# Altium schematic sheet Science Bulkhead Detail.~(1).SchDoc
size B; Organization: Monterey Bay Aquarium Research Institute; Address1: 7700 Sandholdt Rd; Address2: Moss Landing, CA 95039-9644; CompanyName: MBARI
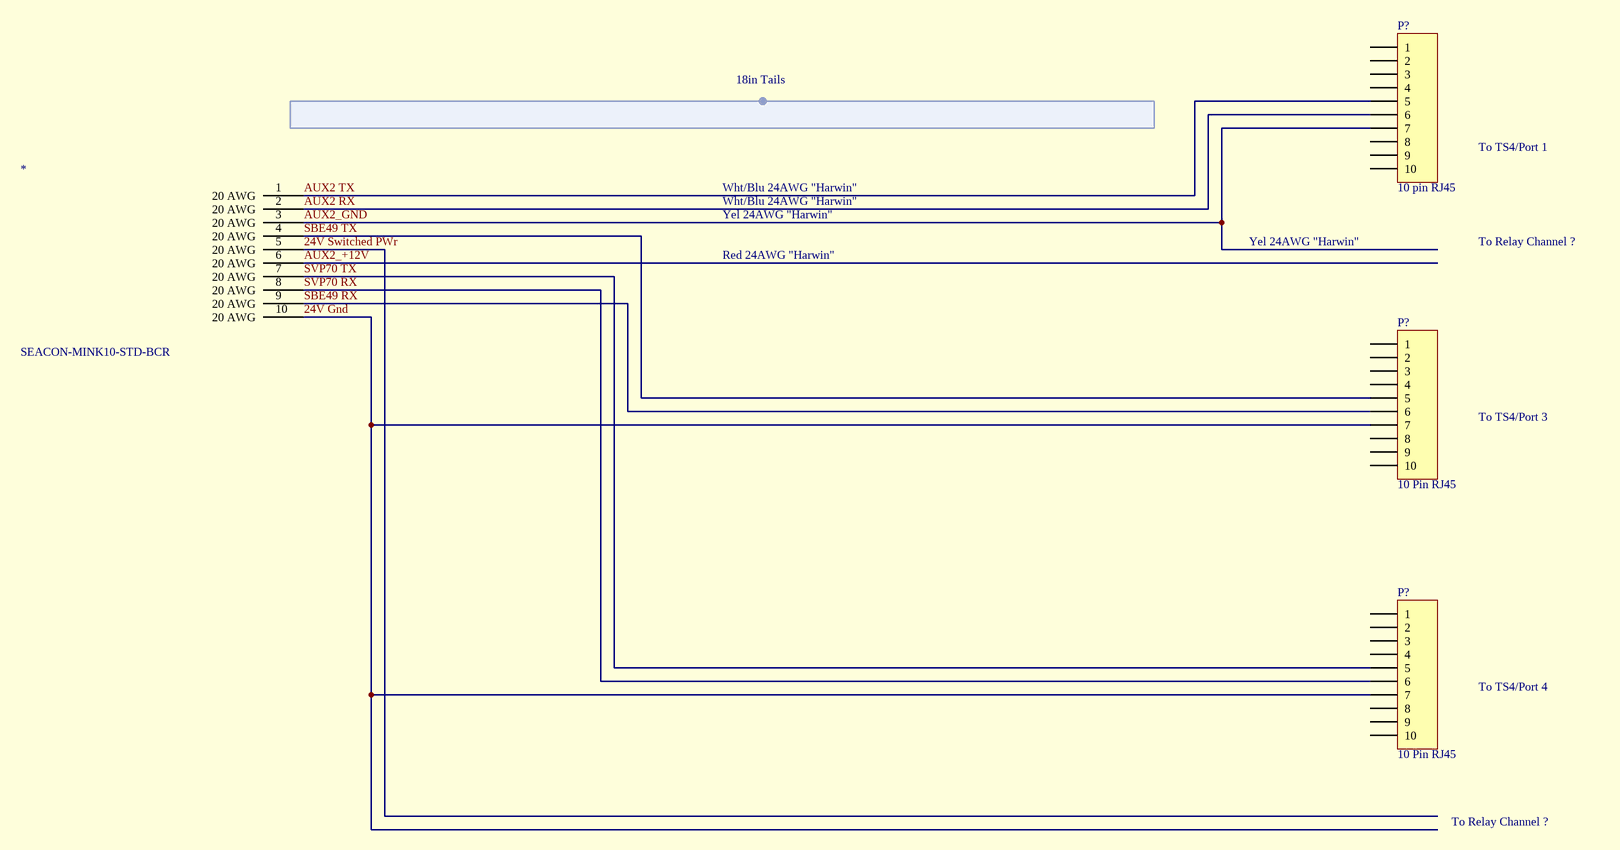
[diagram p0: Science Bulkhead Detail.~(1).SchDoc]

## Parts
(Parts that share a designator on the sheet are numbered #1, #2 ... from top to bottom, then left to right.)
*  SEACON-MINK10-STD-BCR
P?#1  10 pin RJ45  [HDR1X10]
P?#2  10 Pin RJ45  [HDR1X10]
P?#3  10 Pin RJ45  [HDR1X10]

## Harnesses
18in Tails: 

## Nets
24V Gnd: *.10(20_AWG) P?#2.7 P?#3.7
24V Switched PWr: *.5(20_AWG)
AUX2 RX: *.2(20_AWG) P?#1.6
AUX2 TX: *.1(20_AWG) P?#1.5
AUX2_+12V: *.6(20_AWG)
AUX2_GND: *.3(20_AWG) P?#1.7
SBE49 RX: *.9(20_AWG) P?#2.6
SBE49 TX: *.4(20_AWG) P?#2.5
SVP70 RX: *.8(20_AWG) P?#3.6
SVP70 TX: *.7(20_AWG) P?#3.5

Not connected (* = marked no-connect by the designer): P?#1 1 2 3 4 8 9 10; P?#2 1 2 3 4 8 9 10; P?#3 1 2 3 4 8 9 10

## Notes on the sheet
- To TS4/Port 1
- Wht/Blu 24AWG "Harwin"
- Yel 24AWG "Harwin"
- Red 24AWG "Harwin"
- To Relay Channel ?
- To TS4/Port 3
- To TS4/Port 4

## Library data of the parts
* = SEACON-MINK10-STD-BCR: Seacon MINK10 BCR Standard Length
P?#1-P?#3 = Header 10: Header, 10-Pin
